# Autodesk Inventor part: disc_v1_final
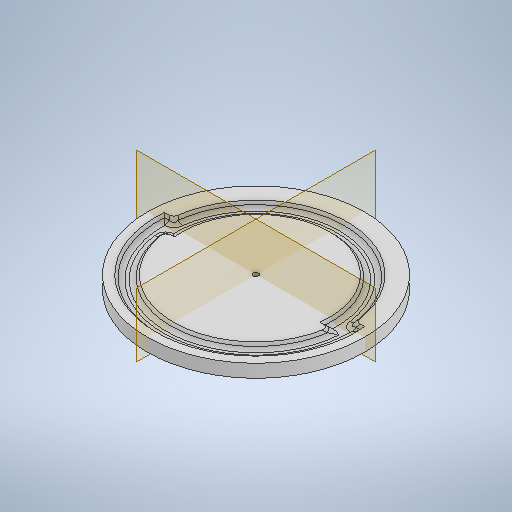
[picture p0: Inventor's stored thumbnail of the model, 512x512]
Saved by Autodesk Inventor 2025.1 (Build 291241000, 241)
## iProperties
Created: 2024-10
Part Number: disc_v1_final
Material: Generic
Document SubType Name: Modeling
Designer: mansa
Density: 1 g/cm^3
Appearance: Default
Author: mansa
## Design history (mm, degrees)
sketch "Sketch1"
  geometry: C1 r 125 at (0, 0); 1 further point
  constraints: 1 centre point, 1 coincident
  dimensions: "d0" = 250 diameter of C1
extrude "Extrusion1" new body sketch "Sketch1" distance "d1" = 15; taper "d2" = 0 deg
sketch "Sketch2"
  geometry: L1 (-168.691, 0)-(186.813, 0); L2 (-99.861, -5.263)-(-89.875, -4.737); L3 (-109.909, 4.471)-(-99.875, 5); L4 (99.875, 5)-(109.862, 5.5); L5 (89.832, -5.503)-(99.875, -5); A1 r 110 centre (0, 0) between (-109.909, 4.471) and (109.862, 5.5); A2 r 90 centre (0, 0) between (89.832, -5.503) and (-89.875, -4.737); A3 r 100 centre (0, 0) between (-99.861, -5.263) and (99.875, -5); A4 r 100 centre (0, 0) between (99.875, 5) and (-99.875, 5); 2 further points
  constraints: 10 end point, 8 point on circle, 4 centre point, 4 line through centre, 3 coincident, 2 parallel, 1 horizontal, 1 midpoint, 1 point on line
  dimensions: "d3" = 220 diameter of A1; "d5" = 180 diameter of A2; "d8" = 10 diameter of point (-94.868, -5) L1; "d9" = 10 diameter of L3.end L1 (= d8); "d10" = 10 diameter of L4.start L1; "d11" = 10 diameter of L5.end L1 (= d10); "d12" = 100 radius of A4; "d13" = 100 radius of A3
sketch "Sketch3"
  geometry: L1 (66.247, 67.848)-(57.562, 64.688); L2 (57.562, 51.009)-(66.247, 47.848); L3 (66.247, 47.848)-(66.247, 67.848) reference; L4 (56.247, 59.848)-(54.247, 59.848); L5 (54.247, 59.848)-(54.247, 55.848); L6 (54.247, 55.848)-(56.247, 55.848); L7 (67.026, 57.848)-(51.03, 57.848) reference; L8 (56.247, 62.808)-(56.247, 59.848); L9 (56.247, 55.848)-(56.247, 52.888); A1 r 2 centre (58.247, 62.808) between (57.562, 64.688) and (56.247, 62.808); A2 r 2 centre (58.247, 52.888) between (56.247, 52.888) and (57.562, 51.009); 4 further points
  constraints: 18 end point, 5 point on circle, 4 tangent, 3 horizontal, 3 parallel, 3 vertical, 2 centre point, 2 midpoint, 1 equal radius, 1 perpendicular, 1 point on line, 1 symmetric about line, 1 other
  dimensions: "d15" = 20 distance of L2.end L1.start; "d20" = 4 distance between parallel lines of L6 L4; "d21" = 2 distance of L4.start L4.end (= 0.5 x d20); "d22" = 2 radius of A1 (derived); "d24" = 70 deg angle of L1 L3; "d25" = 70 deg angle of L2 L3 (= d24); "d26" = 10 distance from line of L3 point (56.247, 54.368); "d27" = 10 distance between parallel lines of L3 L8 (= d26)
extrude "Extrusion2" cut sketch "Sketch2" distance "d28" = 5; taper "d29" = 0 deg
sketch "Sketch7"
  geometry: L1 (99.875, 5)-(109.862, 5.5) reference; L2 (-109.909, 4.471)-(-99.875, 5) reference; L3 (99.875, -5)-(89.832, -5.503) reference; L4 (-89.875, -4.737)-(-99.861, -5.263) reference; L5 (96.491, 1.326)-(106.484, 1.827); L6 (-106.494, 1.146)-(-96.485, 1.674); L7 (93.482, -1.816)-(103.492, -1.315); L8 (-103.482, -1.949)-(-93.489, -1.422); A1 r 100 centre (0, 0) between (99.875, 5) and (-99.875, 5) reference; A2 r 110 centre (0, 0) between (-109.909, 4.471) and (109.862, 5.5) reference; A3 r 90 centre (0, 0) between (89.832, -5.503) and (-89.875, -4.737) reference; A4 r 100 centre (0, 0) between (-99.861, -5.263) and (99.875, -5) reference; A5 r 96.5 centre (0, 0) between (96.491, 1.326) and (-96.485, 1.674); A6 r 106.5 centre (0, 0) between (-106.494, 1.146) and (106.484, 1.827); A7 r 93.5 centre (0, 0) between (93.482, -1.816) and (-93.489, -1.422); A8 r 103.5 centre (0, 0) between (-103.482, -1.949) and (103.492, -1.315); 1 further point
  constraints: 8 end point, 8 point on circle, 4 centre point, 6 other
  dimensions: "d61" = 3 radial gap between concentric circles of A7 A5; "d62" = 3.5 radial gap between concentric circles of A1 A5
extrude "Extrusion4" cut sketch "Sketch7" distance "d65" = 1; taper "d66" = 0 deg
chamfer "Chamfer9" distance "d67" = 5; stored, may be unused: second distance "d68" = 2, angle "d69" = 45 deg
chamfer "Chamfer10" distance "d70" = 5; stored, may be unused: second distance "d71" = 2, angle "d72" = 45 deg
chamfer "Chamfer11" distance "d73" = 5; stored, may be unused: second distance "d74" = 2, angle "d75" = 45 deg
chamfer "Chamfer12" distance "d76" = 5; stored, may be unused: second distance "d77" = 2, angle "d78" = 45 deg
chamfer "Chamfer13" distance "d82" = 5; stored, may be unused: second distance "d83" = 2, angle "d84" = 45 deg
chamfer "Chamfer14" distance "d85" = 5; stored, may be unused: second distance "d86" = 2, angle "d87" = 45 deg
chamfer "Chamfer15" distance "d88" = 5; stored, may be unused: second distance "d89" = 2, angle "d90" = 45 deg
chamfer "Chamfer16" distance "d91" = 5; stored, may be unused: second distance "d92" = 2, angle "d93" = 45 deg
fillet "Fillet5" dims "d95" = 8
sketch "Sketch8"
  geometry: L1 (2.5, 1.833)-(2.5, -1.833); A1 r 3.1 centre (0, 0) between (2.5, 1.833) and (2.5, -1.833); 1 further point
  constraints: 2 end point, 2 point on circle, 1 centre point, 1 coincident, 1 vertical
  dimensions: "d96" = 6.2 diameter of A1; "d97" = 5.6 dimension on A1 L1
extrude "Extrusion5" cut sketch "Sketch8" distance "d98" = 16.2; taper "d99" = 0 deg
sketch "Sketch9"
  geometry: C1 r 3.1 at (0, 0); A1 r 3.1 centre (0, 0) between (2.5, 1.833) and (2.5, -1.833) reference; 1 further point
  constraints: 1 centre point, 1 coincident, 1 concentric
extrude "Extrusion6" cut sketch "Sketch9" distance "d100" = 3.2; taper "d101" = 0 deg
body "Solid1"
node "Projected Loop2"
other parameters: "d17" = 110 deg, "d18" = 110 deg (= d17), "d19" = 4
